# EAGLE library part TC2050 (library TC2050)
TAG-CONNECT ISP Connector Manufacturer: Tag-Connect Cable for easy In-Circuit PCB Programming. Designed for JTAG 10 pin, suitable for many others. Pin Connection for TC2050 NL. PADDescription 1VTREF 2TMS 3GND 4TCK 5NC 6TDO 7RTCK 8TDI 9!TRST 10RESET ©2009 ROFA.cz Modified 7/2011 by Tim McCarthy-Smith VIDA Products INC
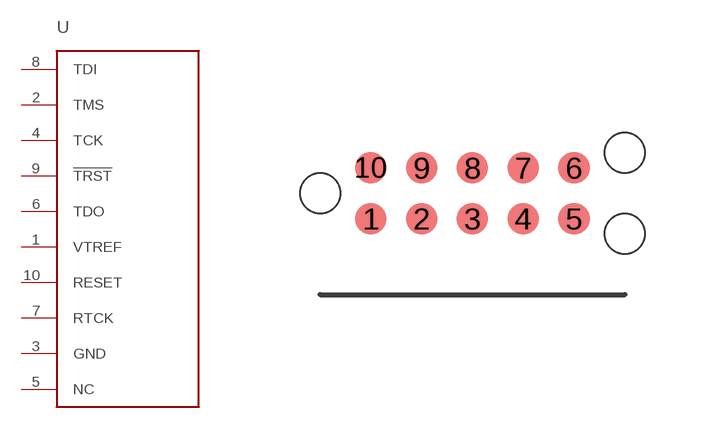
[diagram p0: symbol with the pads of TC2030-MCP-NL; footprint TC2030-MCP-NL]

Designator prefix -

## TC2050-MCP-NL  [TC2030-MCP-NL]
1  VTREF
2  TMS
3  GND
4  TCK
5  NC
6  TDO
7  RTCK
8  TDI
9  !TRST
10  RESET

## Footprint TC2030-MCP-NL (pad centres in mm)
TAG-CONNECT ISP Connector Manufacturer: Tag-Connect Cable for easy In-Circuit PCB Programming. Designed for Standard JTAG 10 Pin, suitable for many others. Footprint for TC2050 NL PADDescription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
smd 0.787 x 0.787: 1 1.27,-0.635; 2 2.54,-0.635; 3 3.81,-0.635; 4 5.08,-0.635; 5 6.35,-0.635; 6 6.35,0.635; 7 5.08,0.635; 8 3.81,0.635; 9 2.54,0.635; 10 1.27,0.635
hole 1 at 0,0
hole 1 at 7.62,-1.016
hole 1 at 7.62,1.016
